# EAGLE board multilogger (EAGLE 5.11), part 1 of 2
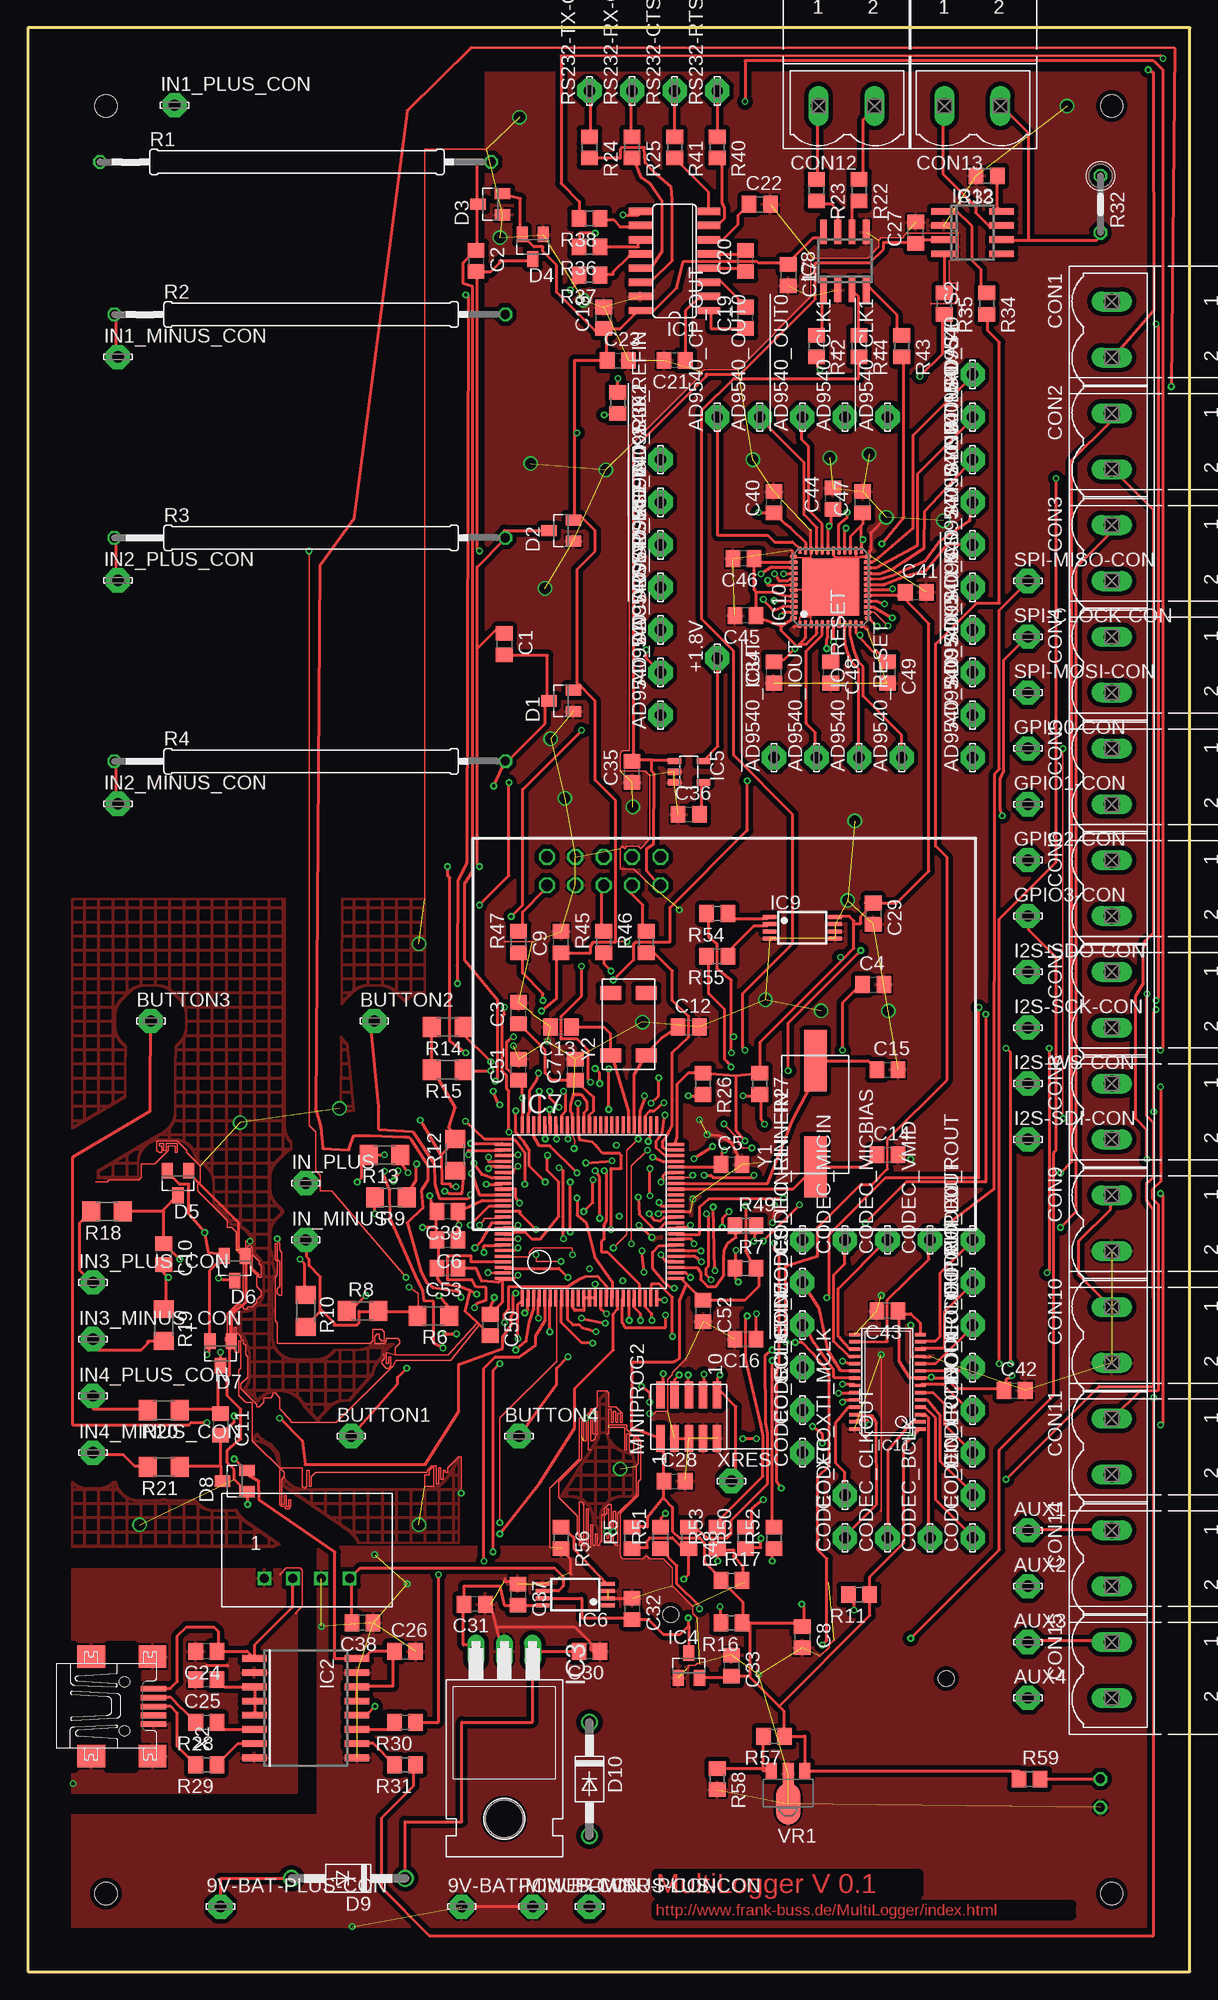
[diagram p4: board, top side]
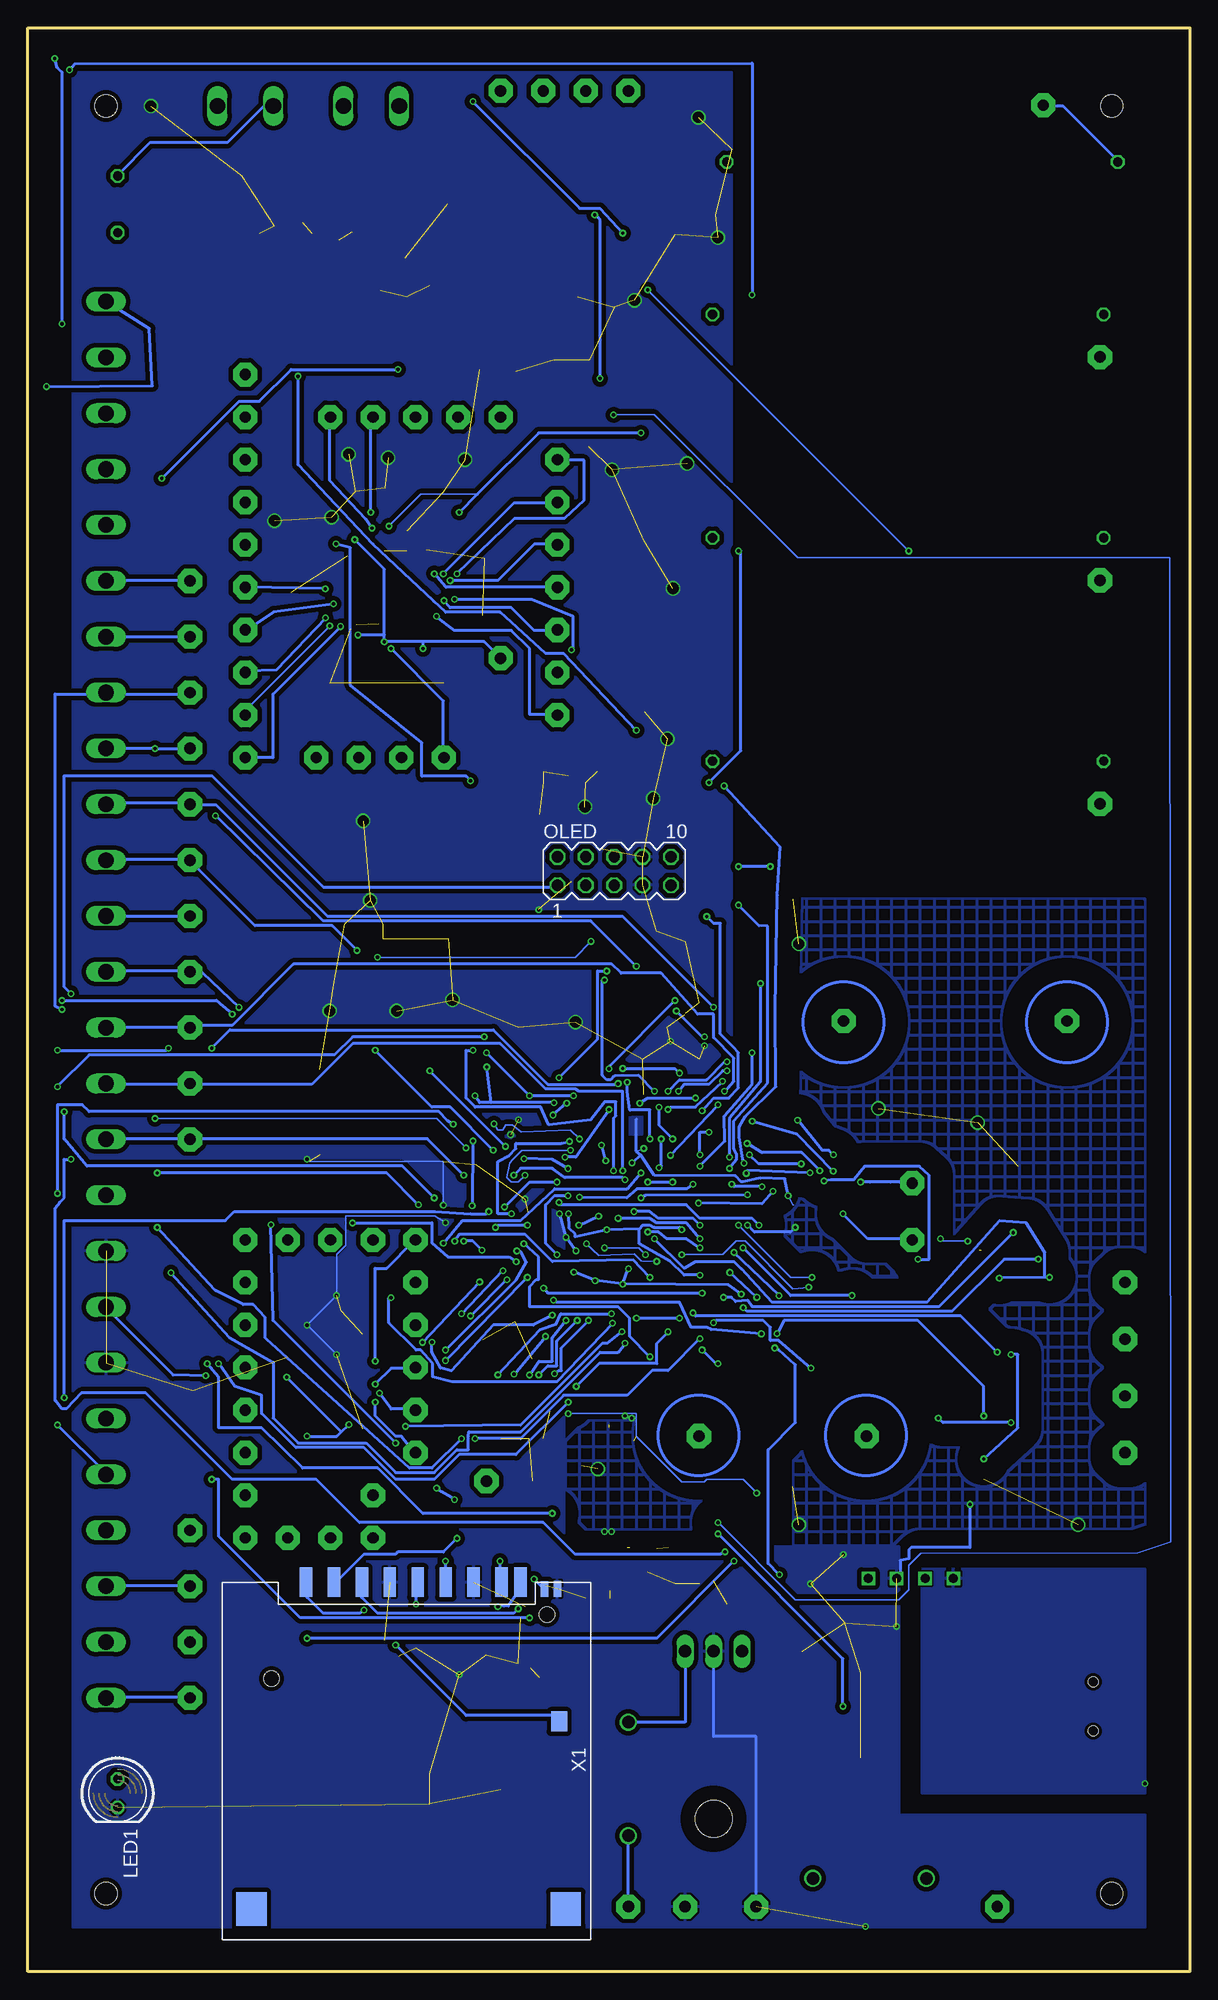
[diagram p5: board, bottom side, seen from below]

Size 104 x 174 mm. Coordinates in mm from the lower left corner, seen from the top.
Outline: 0,0 104,0 104,174 0,174 0,0
Copper layers (1*16): Top 0.035mm / dielectric 1.5mm / Bottom 0.035mm
Design rules "PCB-POOL Standard": minimum track width 0.15mm, minimum drill 0.3mm, track to track 0.15mm, track to pad 0.15mm, pad to pad 0.15mm, via to via 0.15mm, smd to smd 0.15mm, copper to edge 0.3mm, drill to drill 0.2mm, minimum pad ring 0.2mm, minimum via ring 0.15mm, stop-mask expansion 0.075mm, vias tented up to drill 0mil, thermal gap 0.2mm
Holes 2 mm at 7,167 97,167 7,7 97,7

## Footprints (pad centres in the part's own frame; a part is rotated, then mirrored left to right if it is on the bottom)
LSP10 = drill 1.016 pad 2.159 octagon: MP 0,0
C0805 = smd 1.3 x 1.5: 1 -0.95,0; 2 0.95,0
MSTBV2 = drill 1.397 long: 1 -2.5,0; 2 2.5,0
SOT23 = smd 1 x 1.4: 1 -0.95,-1.1; 2 0.95,-1.1; 3 0,1.1
DO41-10 = drill 1.118 round: A 5.08,0; C -5.08,0
SO16 = smd 0.66 x 2.032: 1 -4.445,-3.073; 2 -3.175,-3.073; 3 -1.905,-3.073; 4 -0.635,-3.073; 5 0.635,-3.073; 6 1.905,-3.073; 7 3.175,-3.073; 8 4.445,-3.073; 9 4.445,3.073; 10 3.175,3.073; 11 1.905,3.073; 12 0.635,3.073; 13 -0.635,3.073; 14 -1.905,3.073; 15 -3.175,3.073; 16 -4.445,3.073
SO-16W = smd 0.6 x 2.2: 1 -4.445,-4.6; 2 -3.175,-4.6; 3 -1.905,-4.6; 4 -0.635,-4.6; 5 0.635,-4.6; 6 1.905,-4.6; 7 3.175,-4.6; 8 4.445,-4.6; 9 4.445,4.6; 10 3.175,4.6; 11 1.905,4.6; 12 0.635,4.6; 13 -0.635,4.6; 14 -1.905,4.6; 15 -3.175,4.6; 16 -4.445,4.6
TO220H = drill 1.118 long: 1 -2.54,-10.16; 2 0,-10.16; 3 2.54,-10.16 | hole 3.302: 0,4.826
SOT23-DBV = smd 0.55 x 1.2: 1 -0.95,-1.3; 2 0,-1.3; 3 0.95,-1.3; 4 0.95,1.3; 5 -0.95,1.3
TSSOP8 = smd 1.2 x 0.35: 1 -2.925,0.975; 2 -2.925,0.325; 3 -2.925,-0.325; 4 -2.925,-0.975; 5 2.925,-0.975; 6 2.925,-0.325; 7 2.925,0.325; 8 2.925,0.975
TQFP100 = smd 0.27 x 1.5: 1 -6,-7.75; 2 -5.5,-7.75; 3 -5,-7.75; 4 -4.5,-7.75; 5 -4,-7.75; 6 -3.5,-7.75; 7 -3,-7.75; 8 -2.5,-7.75; 9 -2,-7.75; 10 -1.5,-7.75; 11 -1,-7.75; 12 -0.5,-7.75; 13 0,-7.75; 14 0.5,-7.75; 15 1,-7.75; 16 1.5,-7.75; 17 2,-7.75; 18 2.5,-7.75; 19 3,-7.75; 20 3.5,-7.75; 21 4,-7.75; 22 4.5,-7.75; 23 5,-7.75; 24 5.5,-7.75; 25 6,-7.75; 51 6,7.75; 52 5.5,7.75; 53 5,7.75; 54 4.5,7.75; 55 4,7.75; 56 3.5,7.75; 57 3,7.75; 58 2.5,7.75; 59 2,7.75; 60 1.5,7.75; 61 1,7.75; 62 0.5,7.75; 63 0,7.75; 64 -0.5,7.75; 65 -1,7.75; 66 -1.5,7.75; 67 -2,7.75; 68 -2.5,7.75; 69 -3,7.75; 70 -3.5,7.75; 71 -4,7.75; 72 -4.5,7.75; 73 -5,7.75; 74 -5.5,7.75; 75 -6,7.75 | smd 1.5 x 0.27: 26 7.75,-6; 27 7.75,-5.5; 28 7.75,-5; 29 7.75,-4.5; 30 7.75,-4; 31 7.75,-3.5; 32 7.75,-3; 33 7.75,-2.5; 34 7.75,-2; 35 7.75,-1.5; 36 7.75,-1; 37 7.75,-0.5; 38 7.75,0; 39 7.75,0.5; 40 7.75,1; 41 7.75,1.5; 42 7.75,2; 43 7.75,2.5; 44 7.75,3; 45 7.75,3.5; 46 7.75,4; 47 7.75,4.5; 48 7.75,5; 49 7.75,5.5; 50 7.75,6; 76 -7.75,6; 77 -7.75,5.5; 78 -7.75,5; 79 -7.75,4.5; 80 -7.75,4; 81 -7.75,3.5; 82 -7.75,3; 83 -7.75,2.5; 84 -7.75,2; 85 -7.75,1.5; 86 -7.75,1; 87 -7.75,0.5; 88 -7.75,0; 89 -7.75,-0.5; 90 -7.75,-1; 91 -7.75,-1.5; 92 -7.75,-2; 93 -7.75,-2.5; 94 -7.75,-3; 95 -7.75,-3.5; 96 -7.75,-4; 97 -7.75,-4.5; 98 -7.75,-5; 99 -7.75,-5.5; 100 -7.75,-6
SO08 = smd 0.6 x 2.2: 1 -1.905,-2.6; 2 -0.635,-2.6; 3 0.635,-2.6; 4 1.905,-2.6; 5 1.905,2.6; 6 0.635,2.6; 7 -0.635,2.6; 8 -1.905,2.6
LFCSP48 = smd 0.6 x 0.32: 1 -3.325,2.75; 12 -3.325,-2.75; 25 3.325,-2.75; 36 3.325,2.75 | smd 0.7 x 0.32: 2 -3.3,2.25; 3 -3.3,1.75; 4 -3.3,1.25; 5 -3.3,0.75; 6 -3.3,0.25; 7 -3.3,-0.25; 8 -3.3,-0.75; 9 -3.3,-1.25; 10 -3.3,-1.75; 11 -3.3,-2.25; 26 3.3,-2.25; 27 3.3,-1.75; 28 3.3,-1.25; 29 3.3,-0.75; 30 3.3,-0.25; 31 3.3,0.25; 32 3.3,0.75; 33 3.3,1.25; 34 3.3,1.75; 35 3.3,2.25 | smd 0.32 x 0.6: 13 -2.75,-3.325; 24 2.75,-3.325; 37 2.75,3.325; 48 -2.75,3.325 | smd 0.32 x 0.7: 14 -2.25,-3.3; 15 -1.75,-3.3; 16 -1.25,-3.3; 17 -0.75,-3.3; 18 -0.25,-3.3; 19 0.25,-3.3; 20 0.75,-3.3; 21 1.25,-3.3; 22 1.75,-3.3; 23 2.25,-3.3; 38 2.25,3.3; 39 1.75,3.3; 40 1.25,3.3; 41 0.75,3.3; 42 0.25,3.3; 43 -0.25,3.3; 44 -0.75,3.3; 45 -1.25,3.3; 46 -1.75,3.3; 47 -2.25,3.3 | smd 5.1 x 5.1: EXP 0,0
TSSOP28 = smd 0.305 x 0.991: 1 -4.225,-2.918; 2 -3.575,-2.918; 3 -2.925,-2.918; 4 -2.275,-2.918; 5 -1.625,-2.918; 6 -0.975,-2.918; 7 -0.325,-2.918; 8 0.325,-2.918; 9 0.975,-2.918; 10 1.625,-2.918; 11 2.275,-2.918; 12 2.925,-2.918; 13 3.575,-2.918; 14 4.225,-2.918; 15 4.225,2.918; 16 3.575,2.918; 17 2.925,2.918; 18 2.275,2.918; 19 1.625,2.918; 20 0.975,2.918; 21 0.325,2.918; 22 -0.325,2.918; 23 -0.975,2.918; 24 -1.625,2.918; 25 -2.275,2.918; 26 -2.925,2.918; 27 -3.575,2.918; 28 -4.225,2.918
SOIC8 = smd 0.6 x 2.2: 1 -1.905,-2.6; 2 -0.635,-2.6; 3 0.635,-2.6; 4 1.905,-2.6; 5 1.905,2.6; 6 0.635,2.6; 7 -0.635,2.6; 8 -1.905,2.6
DC-DC-CONVERTER = drill 0.8 square: 1 -3.81,0; 2 -1.27,0; 3 1.27,0; 4 3.81,0
LED5MM = drill 0.813 octagon: A -1.27,0; K 1.27,0
PIN-HEADER-50-MIL-2X5 = smd 2.4 x 0.76: 1 -2.54,2.54; 2 1.36,2.54; 3 -2.54,1.27; 4 1.36,1.27; 5 -2.54,0; 6 1.36,0; 7 -2.54,-1.27; 8 1.36,-1.27; 9 -2.54,-2.54; 10 1.36,-2.54
MA05-2 = drill 1.016 octagon: 1 -5.08,-1.27; 2 -5.08,1.27; 3 -2.54,-1.27; 4 -2.54,1.27; 5 0,-1.27; 6 0,1.27; 7 2.54,-1.27; 8 2.54,1.27; 9 5.08,-1.27; 10 5.08,1.27
0207/35 = drill 0.813 octagon: 1 -7.62,0; 2 27.38,0
R0805 = smd 1.3 x 1.5: 1 -0.95,0; 2 0.95,0
R1206 = smd 1.6 x 1.803: 1 -1.422,0; 2 1.422,0
0207/5V = drill 0.813 octagon: 1 -2.54,0; 2 2.54,0
SOT89 = smd 1 x 1.5: 1 -1.499,-1.981; 3 1.499,-1.981 | smd 1 x 2: 2 0,-1.727 | smd 2.2 x 3.7: 2@1 0,0.94
FPS009-3000 = smd 2.65 x 1.1: 1 -10,-20; 2 -10,-17.5; 3 -10,-15; 4 -10,-12.5; 5 -10,-10; 6 -10,-7.5; 7 -10,-5; 8 -10,-3.3; 9 -10,-22.5 | smd 1.4 x 0.7: COM_TERM -9.396,0; DETECT -9.385,-1.159 | smd 3 x 2.7: M1 19.249,-27.387; M2 19.251,0.741 | smd 1.8 x 1.45: WRITE_PROT 2.464,0.152 | hole 1.4: -7.098,-0.925; -1.38,-25.585
TYCO = smd 2.3 x 0.5: 1 2.9,1.75; 2 2.9,0.95; 3 2.9,0.15; 4 2.9,-0.65; 5 2.9,-1.45 | smd 2.5 x 2: M1 -2.7,-4.3; M2 -2.7,4.6; M3 2.8,4.6; M4 2.8,-4.3 | hole 0.9: 0.3,2.35; 0.3,-2.05
ECS-CRYSTAL = smd 5.5 x 2: 1 -4.9,0.1; 2 4.6,0.1
ABS25-CRYSTAL = smd 1.27 x 1.905: 1 -2.54,0; 2 3.048,0; 3 3.048,3.175; 4 -2.54,3.175

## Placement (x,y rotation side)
9V-BAT-MINUS-CON  LSP10  [LSP10]  38.83,5.81 0 top
9V-BAT-PLUS-CON  LSP10  [LSP10]  17.24,5.81 0 top
!AD9540_CLK1  LSP10  [LSP10]  76.93,139.16 90 top
!AD9540_CLK2  LSP10  [LSP10]  56.61,131.54 90 top
!AD9540_CS  LSP10  [LSP10]  84.55,120.11 90 top
!AD9540_IOUT  LSP10  [LSP10]  66.77,108.68 90 top
!AD9540_OUT0  LSP10  [LSP10]  69.31,139.16 90 top
!AD9540_REFIN  LSP10  [LSP10]  56.61,123.92 90 top
!CODEC_CS  LSP10  [LSP10]  69.31,57.88 90 top
!XRES  LSP10  [LSP10]  62.96,43.91 0 top
+1.8V  LSP10  [LSP10]  61.69,117.57 90 top
AD9540_CLK1  LSP10  [LSP10]  73.12,139.16 90 top
AD9540_CLK2  LSP10  [LSP10]  56.61,127.73 90 top
AD9540_CP_OUT  LSP10  [LSP10]  61.69,139.16 90 top
AD9540_CP_RSET  LSP10  [LSP10]  56.61,120.11 90 top
AD9540_DAC_RSET  LSP10  [LSP10]  56.61,112.49 90 top
AD9540_DRV_RSET  LSP10  [LSP10]  56.61,116.3 90 top
AD9540_IO_RESET  LSP10  [LSP10]  74.39,108.68 90 top
AD9540_IO_UPDATE  LSP10  [LSP10]  84.55,131.54 90 top
AD9540_IOUT  LSP10  [LSP10]  70.58,108.68 90 top
AD9540_OUT0  LSP10  [LSP10]  65.5,139.16 90 top
AD9540_REFIN  LSP10  [LSP10]  56.61,135.35 90 top
AD9540_RESET  LSP10  [LSP10]  78.2,108.68 90 top
AD9540_S0  LSP10  [LSP10]  84.55,135.35 90 top
AD9540_S1  LSP10  [LSP10]  84.55,139.16 90 top
AD9540_S2  LSP10  [LSP10]  84.55,142.97 90 top
AD9540_SCLK  LSP10  [LSP10]  84.55,116.3 90 top
AD9540_SD0  LSP10  [LSP10]  84.55,108.68 90 top
AD9540_SDIO  LSP10  [LSP10]  84.55,112.49 90 top
AD9540_SYNC_IN  LSP10  [LSP10]  84.55,127.73 90 top
AD9540_SYNC_OUT  LSP10  [LSP10]  84.55,123.92 90 top
AUX1  LSP10  [LSP10]  89.5,39.5 0 top
AUX2  LSP10  [LSP10]  89.5,34.5 0 top
AUX3  LSP10  [LSP10]  89.5,29.5 0 top
AUX4  LSP10  [LSP10]  89.5,24.5 0 top
BUTTON1  LSP10  [LSP10]  28.94,47.93 0 top
BUTTON2  LSP10  [LSP10]  31,85.1 0 top
BUTTON3  LSP10  [LSP10]  11,85.1 0 top
BUTTON4  LSP10  [LSP10]  43.94,47.93 0 top
C1  2n2  [C0805]  42.64,118.84 270 top
C2  2n2  [C0805]  40.1,153.13 270 top
C3  1 µ  [C0805]  43.91,85.82 90 top
C4  10 µ  [C0805]  75.66,88.36 0 top
C5  100 n  [C0805]  62.96,72.26 0 top
C6  1 µ  [C0805]  37.56,65.5 180 top
C7  100 n  [C0805]  48.99,80.74 90 top
C8  100n  [C0805]  69.31,29.94 270 top
C9  100n  [C0805]  47.72,92.17 90 top
C10  100 p  [C0805]  12.16,64.23 270 top
C11  100 p  [C0805]  17.24,48.99 270 top
C12  5 p  [C0805]  59.15,84.55 0 top
C13  5 p  [C0805]  47.72,84.55 180 top
C14  22 p  [C0805]  76.93,73.12 0 top
C15  22 p  [C0805]  76.93,80.74 0 top
C16  2n2  [C0805]  64.23,56.61 180 top
C17  100 n  [C0805]  68.04,151.86 270 top
C18  100 n  [C0805]  51.53,148.05 90 top
C19  100 n  [C0805]  64.23,148.05 90 top
C20  100 n  [C0805]  64.23,153.13 90 top
C21  100 n  [C0805]  57.88,144.24 180 top
C22  100 n  [C0805]  65.5,158.21 0 top
C23  10 µ  [C0805]  52.8,144.24 0 top
C24  100n  [C0805]  15.97,28.67 180 top
C25  100n  [C0805]  15.97,26.13 180 top
C26  100n  [C0805]  33.75,28.67 0 top
C27  100 n  [C0805]  79.47,155.67 90 top
C28  100n  [C0805]  57.88,43.91 0 top
C29  100 n  [C0805]  75.66,94.71 270 top
C30  1 µ  [C0805]  50.26,28.67 180 top
C31  100n  [C0805]  40,32.89 180 top
C32  1 µ  [C0805]  54.07,32.48 270 top
C33  1 µ  [C0805]  62.96,27.4 270 top
C34  1 µ  [C0805]  66.77,116.3 90 top
C35  100n  [C0805]  54.07,107.41 90 top
C36  10 n  [C0805]  59.15,103.6 0 top
C37  100n  [C0805]  43.86,33.75 270 top
C38  100n  [C0805]  29.94,31.21 180 top
C39  100 n  [C0805]  37.56,68.04 180 top
C40  100 n  [C0805]  66.77,131.54 90 top
C41  100 n  [C0805]  79.47,123.48 0 top
C42  100 n  [C0805]  88.31,52.04 0 top
C43  100 n  [C0805]  76.93,59.15 180 top
C44  1 µ  [C0805]  72.05,131.86 90 top
C45  100 n  [C0805]  64.23,121.38 180 top
C46  100 n  [C0805]  64.05,126.49 180 top
C47  100 n  [C0805]  74.69,131.54 90 top
C48  100 n  [C0805]  71.85,116.3 270 top
C49  1 µ  [C0805]  76.93,116.3 270 top
C50  1 µ  [C0805]  41.37,57.88 270 top
C51  100 n  [C0805]  43.91,80.74 90 top
C52  100 n  [C0805]  60.42,59.15 270 top
C53  100 n  [C0805]  37.56,62.96 180 top
CODEC_BCLK  LSP10  [LSP10]  80.74,38.83 90 top
CODEC_CLKOUT  LSP10  [LSP10]  76.93,38.83 90 top
CODEC_DIN  LSP10  [LSP10]  84.55,38.83 90 top
CODEC_DOUT  LSP10  [LSP10]  84.55,46.45 90 top
CODEC_LHPOUT  LSP10  [LSP10]  84.55,54.07 90 top
CODEC_LLINEIN  LSP10  [LSP10]  69.31,61.69 90 top
CODEC_LOUT  LSP10  [LSP10]  84.55,61.69 90 top
CODEC_LRCIN  LSP10  [LSP10]  84.55,42.64 90 top
CODEC_LRCOUT  LSP10  [LSP10]  84.55,50.26 90 top
CODEC_MICBIAS  LSP10  [LSP10]  76.93,65.5 90 top
CODEC_MICIN  LSP10  [LSP10]  73.12,65.5 90 top
CODEC_MODE  LSP10  [LSP10]  69.31,54.07 90 top
CODEC_RHPOUT  LSP10  [LSP10]  84.55,57.88 90 top
CODEC_RLINEIN  LSP10  [LSP10]  69.31,65.5 90 top
CODEC_ROUT  LSP10  [LSP10]  84.55,65.5 90 top
CODEC_SCLK  LSP10  [LSP10]  69.31,46.45 90 top
CODEC_SDIN  LSP10  [LSP10]  69.31,50.26 90 top
CODEC_VMID  LSP10  [LSP10]  80.74,65.5 90 top
CODEC_XTI_MCLK  LSP10  [LSP10]  73.12,42.64 90 top
CODEC_XTO  LSP10  [LSP10]  73.12,38.83 90 top
CON1  [MSTBV2]  97,147 270 top
CON2  [MSTBV2]  97,137 270 top
CON3  [MSTBV2]  97,127 270 top
CON4  [MSTBV2]  97,117 270 top
CON5  [MSTBV2]  97,107 270 top
CON6  [MSTBV2]  97,97 270 top
CON7  [MSTBV2]  97,87 270 top
CON8  [MSTBV2]  97,77 270 top
CON9  [MSTBV2]  97,67 270 top
CON10  [MSTBV2]  97,57 270 top
CON11  [MSTBV2]  97,47 270 top
CON12  [MSTBV2]  73.27,167 0 top
CON13  [MSTBV2]  84.54,167 0 top
CON14  [MSTBV2]  97,37 270 top
CON15  [MSTBV2]  97,27 270 top
D1  BAV199  [SOT23]  47.72,113.76 90 top
D2  BAV199  [SOT23]  47.72,129 90 top
D3  BAV199  [SOT23]  41.37,158.21 90 top
D4  BAV199  [SOT23]  45.18,154.4 180 top
D5  BAV199  [SOT23]  13.43,70.58 180 top
D6  BAV199  [SOT23]  18.51,62.96 180 top
D7  BAV199  [SOT23]  17.24,55.34 180 top
D8  BAV199  [SOT23]  18.51,43.91 90 top
D9  1N4004  [DO41-10]  28.67,8.35 180 top
D10  1N4004  [DO41-10]  50.26,17.24 270 top
GPIO0-CON  LSP10  [LSP10]  89.5,109.5 0 top
GPIO1-CON  LSP10  [LSP10]  89.5,104.5 0 top
GPIO2-CON  LSP10  [LSP10]  89.5,99.5 0 top
GPIO3-CON  LSP10  [LSP10]  89.5,94.5 0 top
I2S-SCK-CON  LSP10  [LSP10]  89.5,84.5 0 top
I2S-SDI-CON  LSP10  [LSP10]  89.5,74.5 0 top
I2S-SDO-CON  LSP10  [LSP10]  89.5,89.5 0 top
I2S-WS-CON  LSP10  [LSP10]  89.5,79.5 0 top
IC1  MAX3232CSE  [SO16]  57.88,153.13 90 top
IC2  ADUM4160  [SO-16W]  24.86,23.59 270 top
IC3  7805T  [TO220H]  42.64,18.51 180 top
IC4  MCP1703CB  [SOT23]  59.15,27.4 0 top
IC5  TPS79118  [SOT23-DBV]  59.15,107.41 270 top
IC6  TPS2112  [TSSOP8]  48.99,33.75 180 top
IC7  PSOC5  [TQFP100]  50.26,68.04 0 top
IC8  ST3485E  [SO08]  73.12,153.13 0 top
IC9  SE95  [TSSOP8]  69.31,93.44 0 top
IC10  AD9540  [LFCSP48]  71.85,123.92 90 top
IC11  TLV320AIC23  [TSSOP28]  76.93,52.8 90 top
IC12  SN65HVD232D  [SOIC8]  84.55,155.67 270 top
IC13  DC-DC-CONVERTER  [DC-DC-CONVERTER]  24.98,35.19 0 top
IN1_MINUS_CON  LSP10  [LSP10]  8.05,144.54 0 top
IN1_PLUS_CON  LSP10  [LSP10]  13.13,167.08 0 top
IN2_MINUS_CON  LSP10  [LSP10]  8.05,104.54 0 top
IN2_PLUS_CON  LSP10  [LSP10]  8.05,124.54 0 top
IN3_MINUS_CON  LSP10  [LSP10]  5.81,56.61 0 top
IN3_PLUS_CON  LSP10  [LSP10]  5.81,61.69 0 top
IN4_MINUS_CON  LSP10  [LSP10]  5.81,46.45 0 top
IN4_PLUS_CON  LSP10  [LSP10]  5.81,51.53 0 top
IN_MINUS  LSP10  [LSP10]  24.86,65.5 0 top
IN_PLUS  LSP10  [LSP10]  24.86,70.58 0 top
LED1  [LED5MM]  95.98,15.97 270 bottom
MINIPROG2  PIN-HEADER  [PIN-HEADER-50-MIL-2X5]  59.15,50.26 90 top
OLED  OLED  [MA05-2]  51.53,98.52 0 bottom
POWER-MINUS-CON  LSP10  [LSP10]  45.18,5.81 0 top
POWER-PLUS-CON  LSP10  [LSP10]  50.26,5.81 0 top
R1  10 Meg  [0207/35]  14.08,162 0 top
R2  10 Meg  [0207/35]  15.35,148.35 0 top
R3  10 Meg  [0207/35]  15.35,128.35 0 top
R4  10 Meg  [0207/35]  15.35,108.35 0 top
R5  10 k  [R0805]  54.07,38.83 90 top
R6  10 Meg  [R1206]  36.29,58.71 180 top
R7  10 k  [R0805]  64.23,62.96 0 top
R8  1 Meg  [R1206]  29.94,59.15 0 top
R9  100 k  [R1206]  32.48,69.31 180 top
R10  10 k  [R1206]  24.86,59.15 270 top
R11  50 k  [R0805]  74.39,33.75 180 top
R12  10 Meg  [R1206]  38.26,73.12 90 top
R13  1 Meg  [R1206]  31.91,73.12 180 top
R14  100 k  [R1206]  37.56,84.55 180 top
R15  10 k  [R1206]  37.56,80.74 180 top
R16  50 k  [R0805]  62.96,31.21 180 top
R17  50 k  [R0805]  62.96,35.02 0 top
R18  100 k  [R1206]  7.08,68.04 180 top
R19  100 k  [R1206]  12.16,57.88 270 top
R20  100 k  [R1206]  12.16,50.26 180 top
R21  100 k  [R1206]  12.16,45.18 180 top
R22  100  [R0805]  74.39,159.48 270 top
R23  100  [R0805]  70.58,159.48 270 top
R24  100  [R0805]  50.26,163.29 270 top
R25  100  [R0805]  54.07,163.29 270 top
R26  2k2  [R0805]  60.42,79.47 270 top
R27  2k2  [R0805]  65.5,79.47 270 top
R28  24  [R0805]  15.97,22.32 180 top
R29  24  [R0805]  15.97,18.51 180 top
R30  24  [R0805]  33.75,22.32 180 top
R31  24  [R0805]  33.75,18.51 180 top
R32  60  [0207/5V]  95.98,158.21 270 top
R33  10k  [R0805]  85.82,160.75 180 top
R34  33  [R0805]  85.82,149.32 270 top
R35  33  [R0805]  82.01,149.32 270 top
R36  24  [R0805]  50.26,154.4 180 top
R37  24  [R0805]  50.26,151.86 180 top
R38  24  [R0805]  50.26,156.94 180 top
R39  24  [R0805]  52.8,140.43 270 top
R40  100  [R0805]  61.69,163.29 270 top
R41  100  [R0805]  57.88,163.29 270 top
R42  24  [R0805]  70.58,145.51 270 top
R43  24  [R0805]  78.2,145.51 270 top
R44  24  [R0805]  74.39,145.51 270 top
R45  24  [R0805]  51.53,92.17 90 top
R46  24  [R0805]  55.34,92.17 90 top
R47  24  [R0805]  43.91,92.17 90 top
R48  24  [R0805]  59.15,38.83 270 top
R49  24  [R0805]  64.23,66.77 0 top
R50  24  [R0805]  64.23,38.83 90 top
R51  24  [R0805]  56.61,38.83 90 top
R52  24  [R0805]  66.77,38.83 90 top
R53  24  [R0805]  61.69,38.83 90 top
R54  24  [R0805]  61.69,94.71 180 top
R55  24  [R0805]  61.69,90.9 180 top
R56  825  [R0805]  47.72,38.83 270 top
R57  2700  [R0805]  66.77,21.05 180 top
R58  6800  [R0805]  61.69,17.24 270 top
R59  330  [R0805]  89.63,17.24 0 top
RS232-CTS-CON  LSP10  [LSP10]  57.88,168.37 90 top
RS232-RTS-CON  LSP10  [LSP10]  61.69,168.37 90 top
RS232-RX-CON  LSP10  [LSP10]  54.07,168.37 90 top
RS232-TX-CON  LSP10  [LSP10]  50.26,168.37 90 top
SPI-CLOCK-CON  LSP10  [LSP10]  89.5,119.5 0 top
SPI-MISO-CON  LSP10  [LSP10]  89.5,124.5 0 top
SPI-MOSI-CON  LSP10  [LSP10]  89.5,114.5 0 top
VR1  [SOT89]  68.04,15.97 180 top
X1  SD-CARD  [FPS009-3000]  56.61,24.86 270 bottom
X2  MINI-USB-SHIELD-UX60-MB-5ST  [TYCO]  8.35,23.59 0 top
Y1  24 MHz  [ECS-CRYSTAL]  70.58,76.93 90 top
Y2  32.768 kHz  [ABS25-CRYSTAL]  55.34,84.55 90 top

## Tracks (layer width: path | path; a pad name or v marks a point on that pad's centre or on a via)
!XRES  (via drill 0.3)
  Top 0.254: v51.78,58.9 51.25,59.3 51.25,60.12 IC7.15 | v61.94,53.41 61.74,53.21 61.74,52.19 | 61.74,52.19 61.74,51.78 MINIPROG2.10 61.74,52.19 | 61.74,52.19 63.37,50.56 63.37,44.47 62.96,44.06 !XRES.MP
  Bottom 0.254: v51.78,58.9 56.3,58.9 56.71,57.98 58.13,57.47 v61.94,53.41
+1.8V  (via drill 0.3)
  Top 0.254: v72.1,119.04 72.1,117.5 C48.1 | v72.1,119.04 IC10.7 | IC10.11 74.12,119.84 74.29,119.63 | 74.29,119.63 75.56,118.23 75.95,118.23 C49.1 | IC10.27 73.6,128.46 74.6,129.46 | C47.1 74.75,130.54 74.75,129.61 74.6,129.46 | 74.6,128.19 IC10.25 | 74.6,128.19 74.6,129.46 | IC10.38 65.47,126.17 C46.1 64.99,126.36 64.99,123.72 65.19,123.51 | 67.43,120.47 65.39,121.17 C45.1 65.19,121.48 65.19,123.51 | 67.43,120.47 IC10.48 | 65.19,123.51 66.82,123.51 67.55,123.23 68.45,123.11 IC10.44 | 68.85,118.64 v68.65,118.43 67.63,117.42 66.82,117.42 C34.2 | 68.85,118.64 69.06,118.84 | 69.06,118.84 69.6,119.45 69.6,120.47 IC10.2 | 69.06,118.84 69.67,118.84 70.48,119.65 70.61,119.83 70.61,120.47 IC10.4 | 68.85,118.64 67.43,120.06 67.43,120.47 | IC5.5 60.52,108.48 61.74,109.7 61.74,117.42 +1.8V.MP | v72.1,119.04 | v74.75,128.19 74.6,128.19 | v74.47,119.65 74.29,119.63
  Bottom 0.254: 68.65,119.04 63.16,119.04 +1.8V.MP | 68.65,119.04 v72.1,119.04 72.1,119.65 | v74.75,128.19 72.1,125.55 72.1,119.65 | 72.1,119.65 v74.47,119.65 | 68.65,119.04 v68.65,118.43
+3V3  (via drill 0.3)
  Top 0.15: 52.6,92.22 v53.61,92.22 | v72.71,90.8 72.92,90.59
  Top 0.254: IC4.2 62.96,26.3 C33.2 64.59,26.45 | 64.59,26.45 64.59,31.26 63.98,31.26 | 63.98,31.26 63.91,31.26 R16.1 | R16.1 69.31,31.21 C8.1 69.46,31.06 69.46,32.68 v69.26,32.89 | R59.1 88.68,17.95 VR1.1 69.54,21.1 69.46,21.1 69.46,21.05 R57.1 67.63,21.1 67.63,23.34 67.23,23.74 | IC7.26 58.48,62.04 58.94,61.58 | 58.94,61.58 C52.1 64.16,60.1 65.4,61.33 65.4,62.74 R7.2 64.99,62.96 64.24,64.47 64.23,67.41 64.23,68.45 v64.24,68.57 | IC7.100 42.51,59.97 C50.1 41.22,58.9 41.22,59.1 v41.74,60.36 | IC7.100 42.45,62.01 42.13,61.69 40.61,61.82 40.13,62.93 39.75,62.93 C53.1 | v44.26,78.2 IC7.75 | v44.26,78.2 44.26,79.44 C51.1 43.86,79.83 42.84,80.84 42.84,83.2 v43.45,83.69 | IC10.17 77.77,123.17 78.14,123.23 | 78.14,123.23 C41.1 | IC10.31 71.6,129.31 v71.7,129.41 71.9,129.61 71.9,130.44 C44.1 | 80.84,53.12 IC11.8 79.7,53.14 78.91,53.14 78,54.63 78,58.9 C43.1 78.13,58.9 79.01,58.9 79.85,58.06 IC11.14 | 80.84,53.12 82.14,53.12 83.08,52.19 87.21,52.19 C42.1 87.55,52.19 87.55,53 v88.08,53.35 | 51.78,147.09 51.55,147.09 C18.1 | 51.78,147.09 53,147.09 54.6,148.69 IC1.16 54.83,148.51 55.85,148.51 58.08,150.74 58.66,153.12 65.25,153.12 65.39,152.98 68.04,152.98 | 63.37,80.17 R26.1 60.32,80.44 59.1,80.44 58.08,79.42 58.08,74.69 57.88,74.14 IC7.50 | 63.37,80.17 R27.1 65.5,83.18 72.92,90.59 73.93,91.61 73.93,93.85 | 73.93,93.85 73.93,94.05 73.53,94.46 72.28,94.46 IC9.8 | C29.1 74.93,95.66 | C29.1 77.78,95.66 80.64,98.52 80.64,120.67 78.14,123.23 | IC10.35 69.6,127.92 68.24,129.25 67.75,129.61 C40.1 66.62,130.63 v65.4,130.63 | 56.86,42.39 55.44,40.61 55.44,39.8 54.22,39.8 R5.2 | 56.86,42.39 56.86,43.86 C28.1 56.86,44.06 56.86,47.52 56.66,47.72
  Top 0.254: 56.66,47.72 54.02,48.74 54.05,54.55 57.7,54.55 57.91,54.6 58.29,54.88 58.29,60.1 58.94,61.58 | 56.66,47.72 MINIPROG2.1 | 63.98,31.26 63.98,33.09 62.15,34.92 R17.1 61.94,35.12 61.94,35.25 60.52,36.67 60.52,38.37 60.14,38.83 58.31,38.83 57.68,39.39 57.68,41.57 56.86,42.39 | 63.98,31.26 R16.1 | 67.23,23.74 64.59,26.38 64.59,26.45 | CON10.1 96.89,59.51 94.05,62.35 94.05,65.4 96.89,68.24 96.89,69.46 CON9.1 | 79.22,47.92 78.4,47.11 78.4,38.37 75.36,35.33 75.36,33.9 R11.1 75.36,33.7 75.36,31.87 67.23,23.74 | 79.22,47.92 79.83,48.53 IC11.1 | v75.28,48.95 75.15,49.35 74.14,49.35 IC11.27 | 79.22,47.92 v79.01,47.92 | v80.84,53.21 80.84,53.12 | IC2.13 29.43,24.35 29.43,25.37 IC2.14 29.64,25.57 32.68,25.57 32.68,28.62 C26.1 30.7,28.67 30.04,28.01 29.48,28.01 IC2.16 29.43,28.01 27.46,28.01 27.46,37.56 20.69,42.23 20.67,43.88 19.68,44.47 19.68,44.67 D8.2 19.48,44.88 v18.46,45.89 | v16.02,55.24 16.22,55.44 16.22,56.25 D7.2 16.29,62.79 D6.2 17.44,64.18 16.17,64.34 v15.82,66.16 14.39,67.84 14.39,70.48 13.58,70.48 12.57,71.49 D5.2 | v45.48,66.41 44.06,67.84 44.06,68.04 IC7.88 | v43.86,62.35 43.45,61.94 42.64,61.94 IC7.100 | v55.61,67.84 56.04,67.27 56.61,67.22 56.93,67.53 57.88,67.53 IC7.37 | 47.72,91.2 47.31,90.8 47.31,87.09 v45.97,86 | v49.24,77.74 49.27,77.59 49.27,75.97 IC7.65 49.27,75.76 49.4,74.44 50.15,74.31 50.53,74.25 50.77,74.01 51.02,73.69 51.47,73.25 52.93,73.25 53.12,73.06 53.12,71.91 52.19,71.9 v52.19,66.41 | v44.27,78.2 v44.26,78.2 | 73.93,93.85 74.54,93.85 74.54,94.46 75.56,95.47 C29.1 | 68.04,152.98 70.28,155.21 71.09,155.21 71.09,155.62 IC8.8
  Top 0.254: D3.2 42.64,159.07 44.06,158.72 44.06,155.62 D4.2 44.27,155.42 45.28,154.4 46.09,154.4 46.09,153.99 47.31,152.77 47.31,150.34 50.77,146.88 51.38,146.88 51.38,147.09 C18.1 | 51.78,144.24 51.78,147.09 | 51.78,147.09 C18.1 | 49.14,115.39 49.14,125.55 50.77,127.17 50.77,129 49.55,130.22 48.94,130.22 | 49.14,115.39 49.14,114.98 48.94,114.78 D1.2 | 48.94,130.22 48.94,130.02 D2.2 48.94,130.22 | 51.78,144.24 48.94,144.24 48.94,137.74 | 48.94,130.22 48.94,137.74 | 51.78,144.24 C23.1 | 68.04,152.98 C17.1 | 48.94,137.74 v49.14,137.74 | 47.72,91.2 50.36,91.2 50.36,91.81 50.58,92.16 52.6,92.16 52.6,92.22 52.6,104.82 50.77,106.65 50.77,113.76 49.14,115.39 | 47.72,91.2 C9.1 | v64.18,74.35 63.37,75.36 63.37,80.17 | 63.37,80.17 63.37,80.18
  Bottom 0.15: v71.7,129.41 68.85,132.25 63.77,132.25 | v53.61,92.22 55.03,90.8 v72.71,90.8
  Bottom 0.254: v69.26,32.89 69.26,34.72 X1.4 | 75.97,48.33 76.37,47.92 v79.01,47.92 | 75.97,48.33 v75.28,48.95 | 75.97,48.33 v80.84,53.21 | v88.08,53.35 91,53.41 96.89,59.3 CON10.1 | v18.46,45.89 15.41,48.69 15.41,55.24 v16.02,55.24 | v45.48,66.41 45.69,66.62 47.94,66.62 48.33,66.82 48.99,66.82 49.27,66.48 | 49.27,66.48 49.27,65.16 46.5,63.57 45.28,62.35 v43.86,62.35 | v55.61,67.84 55.53,66.52 55.03,66.02 55.03,65.78 v52.19,66.41 49.27,66.48 | v45.97,86 43.66,83.69 v43.45,83.69 | v49.24,77.74 48.53,78.2 v44.27,78.2 | v65.4,130.63 63.77,132.25 58.29,137.74 v49.14,137.74 | v41.74,60.36 41.05,60.36 40.67,59.98 39.59,60.1 39.19,59.51 22.47,59.51 v15.82,66.16 | v64.18,74.35 v64.24,68.57
+5V  (via drill 0.3)
  Top 0.254: IC6.7 49.55,33.42 49.55,31.67 54.07,31.67 C32.2 55.53,31.53 56.86,30.19 58.39,30.19 59.15,30.96 | 59.15,30.96 IC4.3 | 59.15,30.96 59.15,31.53 59.1,31.53 v59.1,31.67 | IC12.3 79.78,155.03 C27.1 79.42,154.81 76.57,154.81 76.57,154.2 75.36,152.98 70.48,152.98 70.48,149.73 63.77,143.02 60.73,143.02 60.73,142.82 54.22,136.31 54.22,108.48 | 55.85,108.48 54.22,108.48 | 55.85,108.48 57.68,108.48 IC5.1 | 55.85,108.48 55.85,107.46 56.05,107.26 56,100.93 55.37,100.53 55.39,98.52 56.46,97.3 OLED.1 | 54.22,108.48 C35.2 | v87.55,44.06 95.88,52.39 100.75,52.39 100.73,68.19 100.12,68.98 100.12,70.56 100.78,71.09 100.75,75.97 100.15,76.57 v100.15,87.55
  Bottom 0.254: v59.1,31.67 79.62,31.67 86.94,38.98 86.94,44.06 v87.55,44.06 | v100.15,87.55 100.75,88.16 100.75,107.05 87.55,107.05 77.59,97.1 56.66,97.1 OLED.1
+5V/2
  Top 0.254: IC13.2 23.71,32.65 20.29,29.23 20.29,28.06 IC2.1 19.62,28.67 C24.1 17.04,28.79 17.04,30.45 16.63,30.85 14.19,30.85 13.38,30.04 13.38,25.98 12.74,25.34 X2.1
CAN_RX  (via drill 0.3)
  Top 0.254: v43.86,64.79 43.66,64.59 42.64,64.59 IC7.95 | v48.53,66.21 v48.53,70.68 | v46.3,70.68 44.88,72.1 44.88,73.53 44.32,74.34 44.06,74.62 43.66,75.15 v43.66,77.06 | v43.25,94.46 44.27,95.47 44.27,105.83 v49.55,111.12 | v79.83,142.82 81.86,144.85 81.86,148.3 R35.2
  Bottom 0.254: v43.86,64.79 45.05,65.6 46.79,65.6 47.53,66.21 v48.53,66.21 | v48.53,70.68 v46.3,70.68 | v43.66,77.06 42.64,78.2 41.26,78.2 40.41,79.11 40.41,82.26 40.81,82.71 42.03,83.93 42.03,93.85 42.64,93.85 v43.25,94.46 | v49.55,111.12 56.05,118 57.68,118 61.74,121.69 66.62,121.69 67.7,122.69 73.12,127.79 79.83,134.89 v79.83,142.82
CAN_TX  (via drill 0.3)
  Top 0.203: 76.92,71.84 76.92,74.48
  Top 0.254: v57.07,58.76 57.07,57.68 53.42,57.68 53.21,58.08 53.21,60.12 IC7.19 | v67.84,56.34 67.84,63.19 70.68,64.05 70.68,66.62 74.54,70.48 75.56,70.48 76.92,71.84 | 76.92,74.48 82.26,79.83 82.26,99.74 81.25,100.75 81.25,118.84 84.91,122.5 86.94,122.5 86.94,145.87 85.92,146.88 85.92,148.3 R34.2
  Bottom 0.254: v57.07,58.76 58.77,57.88 62.38,57.88 66.1,53.78 67.08,54.03 67.84,55.49 v67.84,56.34
CANH
  Top 0.254: IC12.7 86,156.31 84.83,157.47 84.83,157.98 81.88,160.93 81.88,166.84 CON13.1
  Bottom 0.254: R32.1 95.88,160.9 93.03,163.75 86.12,163.75 82.87,167 82.06,167 CON13.1
CANL
  Top 0.254: 89.58,155.01 95.67,155.01 95.88,155.21 95.88,155.62 R32.2 | 89.58,155.01 87.34,155.01 IC12.6 | 89.58,155.01 89.58,164.56 87.14,167 CON13.2
CMOD  (via drill 0.3)
  Top 0.254: v65.19,58.9 65.19,56.66 C16.1 | v61.49,62.76 v61.33,68.45 | v56.66,70.68 56.86,70.89 56.86,71.29 57.07,71.49 57.88,71.49 IC7.45
  Bottom 0.254: v65.19,58.9 v61.49,62.76 | v61.33,68.45 59.1,70.68 v56.66,70.68
D1KM  (via drill 0.3)
  Top 0.254: v39.63,74.14 42.44,74.14 IC7.76 | v33.13,71.7 33.13,71.44 v32.75,70.78 | v24.35,63.77 24.76,63.37 24.76,60.73 R10.1
  Bottom 0.254: v39.63,74.14 38.31,73.32 34.75,73.32 v33.13,71.7 | v32.75,70.78 32.11,70.89 30.08,70.89 29.13,72.09 24.21,72.09 23.35,71.29 23.35,63.77 v24.35,63.77
D1KP  (via drill 0.3)
  Top 0.254: v45.76,78.81 45.76,75.77 IC7.72 | v41.42,80.64 38.98,80.64 R15.1
  Bottom 0.254: v45.76,78.81 45.28,79.42 43.05,79.42 41.83,80.64 v41.42,80.64
D1M  (via drill 0.3)
  Top 0.254: v40.81,64.38 40.81,64.99 42.44,64.99 IC7.94 | v36.77,60.51 37.56,59.53 37.56,59.3 R6.1
  Bottom 0.254: v36.77,60.51 v40.81,64.38
D1P  (via drill 0.3)
  Top 0.254: v43.99,68.8 43.66,69.26 43.66,70.07 42.64,70.07 IC7.84 | v37.31,69.87 37.7,69.67 38.85,69.67 39.05,71.7 R12.1
  Bottom 0.254: v43.99,68.8 38.31,68.74 v37.31,69.87
D10M  (via drill 0.3)
  Top 0.254: v40,64.79 40.61,65.4 41.55,67.05 42.44,67.02 IC7.90 | v30.25,60.52 29.03,59.3 28.62,59.3 R8.1
  Bottom 0.254: v40,64.79 35.73,60.52 v30.25,60.52
D10P  (via drill 0.3)
  Top 0.254: v39.71,71.46 40.41,69.54 42.44,69.54 IC7.85 | v34.02,71.51 33.33,72.51 R13.1 | R13.1
  Bottom 0.254: v39.71,71.46 39.63,71.7 v34.02,71.51
D100M  (via drill 0.3)
  Top 0.254: v39.43,73.12 39.43,73.53 42.44,73.53 IC7.77 | v34.79,72.31 34.75,71.7 34.75,70.89 33.9,69.46 R9.1
  Bottom 0.254: v39.43,73.12 38.61,72.31 v34.79,72.31
D100P  (via drill 0.3)
  Top 0.254: v46.3,74.54 46.3,75.76 IC7.71 | v47.52,77.39 46.7,78.2 v46.7,78.81 | v41.42,81.45 38.98,83.89 38.98,84.5 R14.1
  Bottom 0.254: v46.3,74.54 47.52,75.76 v47.52,77.39 | v46.7,78.81 45.69,79.83 43.25,79.83 41.62,81.45 v41.42,81.45
DM  (via drill 0.3)
  Top 0.254: v36.75,35.53 36.75,22.32 R30.1 | v37.15,55.82 36.34,56.25 36.31,59.98 35.47,60.04 35.35,61 34.91,61.88 32.43,67.43 32.4,69.93 31.83,71.34 v31.92,71.65 | v39.17,76.12 40.86,74.54 43.4,74.54 43.66,74.39 44.47,73.32 v44.47,70.49 | v54.63,69.32 54.7,67.79 56.04,66.45 56.48,66.45 57.05,67.02 57.88,67.02 IC7.36
  Bottom 0.254: v36.75,35.53 37.76,36.54 37.76,46.7 35.33,49.14 35.33,54.32 36.82,55.63 v37.15,55.82 | v31.92,71.65 35.16,74.95 v39.17,76.12 | v44.47,70.49 45.08,70.07 49.51,70.07 50.45,69.26 v54.63,69.32
DP  (via drill 0.3)
  Top 0.254: v100.75,51.38 100.75,3.22 35.93,3.22 31.67,7.49 31.67,13.79 34.51,16.63 34.51,18.46 R31.1 | v62.76,68.04 62.15,67.43 v62.15,66.62 | v59.3,66.82 59.1,66.62 58.08,66.62 IC7.35
  Bottom 0.254: v100.75,51.38 100.75,67.23 86.33,67.23 85.52,68.04 67.57,68.04 64.38,67.84 62.96,67.84 v62.76,68.04 | v62.15,66.62 61.94,66.82 v59.3,66.82
GND  (via drill 0.3, 0.3 pad 0.25, 1)  (127 unrouted)
  Top 0.15: 45.19,85.69 45.08,85.72 45.13,85.83 | 50.36,46.7 50.16,46.7 50.16,49.75 50.56,50.16 50.97,50.16 50.97,48.13 50.77,47.92 50.77,47.72 50.56,47.52 50.36,47.52 50.36,49.75 50.56,49.95 50.77,49.95 50.77,48.13 50.56,48.13 v50.56,49.75 | v49.95,49.55 49.95,47.52 49.75,47.52 49.75,49.35 49.55,49.35 49.55,45.89 47.52,43.86 47.52,42.44 49.14,40.81 49.14,39.19 49.35,38.98 49.35,38.58 49.55,38.37 49.75,38.37 49.75,41.83 49.55,42.03 49.35,42.03 49.35,39.19 49.55,38.98 49.55,38.58 49.35,38.37 49.35,38.17 49.95,38.17 49.95,41.42 50.16,41.42 50.16,37.97 | 50.36,37.97 50.36,40 50.56,40 50.56,38.17 50.77,38.17 50.77,39.19 50.97,39.19 50.97,38.17 51.17,38.17 51.17,38.37 51.38,38.58 51.38,40.81 51.58,41.01 51.58,41.42 51.99,41.83 52.19,41.83 52.19,38.58 51.58,38.58 51.58,40.81 51.78,41.01 51.78,41.42 51.99,41.42 51.99,38.78 51.78,38.78 v51.78,39.39 | v52.39,39.39 52.39,41.22 52.6,41.22 52.6,39.19 52.39,38.98 52.39,38.37 52.6,38.17 52.8,38.17 52.8,41.01 54.43,42.64 54.43,45.28 54.63,45.48 54.63,47.52 53.61,48.53 53.61,48.94 51.99,48.94 51.99,50.36 52.19,50.36 52.19,49.14 52.39,49.14 52.39,50.16 52.6,50.16 52.6,49.14 52.8,49.14 52.8,49.95 53,49.95 53,49.14 53.21,49.14 53.21,49.95 52.6,50.56 51.99,50.56 51.99,51.78 51.78,51.99 50.97,51.99 50.97,50.56 50.77,50.36 50.36,50.36 50.36,50.16 49.75,49.55 49.35,49.55 49.35,45.89 46.7,43.25 46.7,37.97 | 51.78,48.13 51.99,48.13 51.99,48.74 53.41,48.74 53.41,46.7 53.61,46.7 53.61,48.13 53.82,48.13 53.82,46.7 54.02,46.5 54.22,46.5 54.22,47.72 54.43,47.92 54.63,47.92 54.63,47.72 54.83,47.52 54.83,44.06 54.63,43.86 54.63,42.64 53,41.01 53,37.15 53.21,36.95 55.03,36.95 55.24,37.15 55.44,37.15 55.65,36.95 56.86,36.95 57.68,36.14 57.68,34.51 59.51,32.68 59.51,32.07 59.91,31.67 59.93,31.65
  Top 0.15: v79.01,57.88 79.01,55.03 79.83,55.03 IC11.11 | v76.37,55.24 76.37,41.22 76.32,41.25 | 72.16,29.6 72.1,29.64 71.7,29.23 71.7,29.03 70.89,28.21 70.82,28.27 | v48.89,73.69 48.95,74.42 48.74,74.95 48.74,75.76 IC7.66 | 68.45,127.17 68.34,127.16 | 70.07,126.56 68.65,126.56 IC10.37 | 70.07,126.56 70.07,127.17 IC10.34 | 70.07,123.92 70.07,126.56 | 70.07,123.72 70.07,123.92 | 70.07,121.28 70.07,123.72 | 70.07,121.28 70.07,120.67 IC10.3 | 74.95,120.26 75.06,120.23 | 70.07,123.72 68.65,123.72 IC10.43 | 70.07,123.92 IC10.EXP | 70.07,121.28 69.06,121.28 69.06,120.67 IC10.1 | 41.01,163.14 35.53,163.14 35.53,96.08 35.51,96 | 32.89,55.19 32.07,55.44 32.07,54.43 32.28,54.43 32.28,55.03 32.48,55.03 32.48,54.22 32.28,54.02 32.07,54.02 31.67,54.43 31.67,54.63 31.87,54.83 31.87,55.24 31.79,55.27 | 32.89,55.19 37.62,55.19 40.2,58.08 40.23,58.11 | 60.14,27.53 60.12,27.6 59.91,27.6 59.71,27.4 59.1,27.4 59.1,27.2 59.01,27.13 | 42.64,92.22 45.08,92.22 45.11,92.17 | 32.89,55.19 32.89,55.85 33.29,56.25 33.29,56.46 33.09,56.66 32.07,56.66 32.07,56.46 31.87,56.25 31.06,56.25 31.06,56.86 31.26,57.07 31.46,57.07 31.46,56.66 31.67,56.46 31.87,56.46 31.87,57.27 31.67,57.47 30.85,57.47 30.85,56.46 30.65,56.25 22.32,56.25 22.32,58.08 22.12,58.29 22.12,62.15 22.32,62.35 22.32,63.57 22.12,63.77 22.12,65.19 22.32,65.19 22.32,63.77 22.52,63.57 22.52,61.33 22.32,61.13 22.32,60.73 22.52,60.52 22.73,60.52 22.73,64.38 22.52,64.59 22.52,65.19 22.32,65.4 v22.32,65.6 | v19.88,65.4 19.48,65.4 19.48,64.38 19.88,63.98 19.88,62.96 20.69,62.15 20.9,62.15 20.9,63.16 20.69,63.37 20.69,63.57 20.09,64.18 20.09,64.79 19.88,64.99 19.68,64.99 19.68,64.38 20.09,63.98 20.09,62.96 20.69,62.35 20.49,62.15 20.49,61.33 20.9,60.93 20.9,60.52 20.49,60.12 20.49,59.91 20.09,59.51 19.68,59.51 19.68,59.3 19.27,59.3 19.27,59.51 19.07,59.71 18.87,59.71 18.05,58.9 18.05,56.66 17.85,56.46 17.65,56.46 17.65,56.66 17.85,56.86 17.85,58.9 19.27,60.32 19.27,63.77 19.07,63.98 19.07,64.18 18.66,64.59 18.66,66.21 18.26,66.62 17.85,66.62 17.85,67.23 15.21,69.87 15.21,70.48 15.41,70.68 15.41,72.1 14.19,73.32 14.19,73.53 13.38,74.34 11.55,74.34 11.55,73.53 11.75,73.32 11.96,73.32 11.96,73.53 12.16,73.73 12.16,74.14 11.75,74.14 11.75,73.93 11.96,73.93 11.96,73.73 12.16,73.53 12.36,73.53 12.36,74.14 13.38,74.14 13.38,73.32 13.18,73.32 13.18,73.93 12.57,73.93 12.57,73.53 11.35,72.31 10.13,72.31 10.13,71.09 9.93,70.89 7.28,70.89 7.08,70.68 6.06,70.68
  Top 0.15: 53.21,100.75 53,100.55 53,98.72 54.22,98.72 55.24,97.71 55.31,97.61 | v38.78,42.84 38.78,46.09 38.58,46.09 37.56,45.08 37.56,44.67 37.36,44.67 37.36,44.88 37.15,44.88 37.15,44.06 36.95,44.06 36.95,45.08 36.75,45.08 36.75,43.66 36.54,43.66 36.54,45.28 36.34,45.28 35.93,44.88 35.93,44.47 35.53,44.47 35.53,43.45 36.34,43.45 36.34,45.08 36.14,45.28 35.73,44.88 35.73,44.67 25.77,44.67 25.37,44.27 25.37,43.45 25.16,43.45 25.16,44.88 24.96,44.88 24.96,43.45 24.76,43.25 24.55,43.45 24.55,45.08 22.73,45.08 22.52,44.88 22.52,41.83 22.73,41.62 22.93,41.62 23.13,41.42 23.34,41.42 23.54,41.62 23.54,42.23 23.34,42.23 23.34,41.62 23.13,41.62 23.13,42.64 22.93,42.64 22.93,41.83 22.73,41.83 22.73,44.06 22.93,44.27 22.93,44.67 20.09,47.52 20.09,50.97 19.48,50.97 18.87,51.58 18.87,53.82 19.07,54.02 19.07,56.46 18.87,56.46 18.87,55.44 18.66,55.44 18.46,55.65 18.46,57.68 18.66,57.68 18.66,57.27 19.07,56.86 19.07,56.66 19.27,56.46 19.27,56.25 19.48,56.05 19.48,55.24 19.68,55.03 19.68,53.21 19.07,52.6 19.07,52.19 20.49,50.77 20.49,50.56 20.69,50.56 21.1,50.97 21.1,51.38 21.71,51.38 21.91,51.58 21.91,51.78 22.12,51.78 22.52,51.38 22.52,50.36 23.54,49.35 23.54,49.14 27.6,49.14 32.68,54.22 32.94,54.73 37.83,54.73 40.41,57.88 40.43,57.9 | v55.65,49.95 56.05,49.95 | 56.05,49.95 56.25,50.16 57.27,50.16 57.27,53 57.68,53.41 57.68,53.61 58.9,54.83 58.93,54.7 | 56.05,49.95 56,49.9 | 53.21,100.75 53.41,100.55 53.61,100.75 54.63,100.75 54.83,100.55 55.65,101.36 55.65,107.05 55.24,107.46 53,107.46 53,109.09 53.21,109.29 53.82,109.29 53.82,136.52 60.32,143.02 60.32,143.22 60.52,143.43 63.57,143.43 70.07,149.93 70.07,153.18 70.28,153.38 75.15,153.38 76.17,154.4 76.17,155.01 76.37,155.21 78.4,155.21 78.4,155.42 78.61,155.62 83.28,155.62 83.28,153.18 82.47,153.18 82.47,151.35 82.67,151.15 83.08,151.15 83.08,149.52 82.87,149.32 80.81,149.32
  Top 0.15: 53.21,100.75 53.26,100.73 | v66.63,67.05 v66.82,68.6
  Top 0.254: IC6.2 C32.1 | D5.1 14.39,71.49 18.87,67.02 18.87,64.59 19.27,64.18 D6.1 19.53,63.98 19.53,59.91 18.26,58.9 18.26,56.46 D7.1 18.05,56.25 18.05,53.41 17.85,53.21 17.85,51.55 19.07,50.34 19.07,47.68 17.85,46.65 17.85,45.56 18.46,44.95 18.46,44.06 19.48,43.05 D8.1 19.68,42.84 v19.68,41.83 | 36.75,62.96 36.75,65.4 C6.2 36.54,65.6 36.54,66.62 | 39.57,60.98 39.12,59.1 40.23,58.11 40.43,57.9 41.22,57.07 C50.2 | 39.57,60.98 39.48,60.98 38.7,61.31 36.99,61.56 36.75,61.87 36.7,62.06 36.7,62.33 36.52,62.33 36.75,62.96 | 36.75,62.96 C53.2 | v39.59,66.82 41.27,68.52 42.46,68.52 IC7.87 | 36.54,66.62 v35.33,66.62 | 50.77,60.32 50.36,60.32 IC7.13 50.16,60.32 49.75,60.32 IC7.12 49.75,60.12 49.75,59.17 48.94,59.17 48.74,59.51 48.74,60.12 IC7.10 | 48.74,75.97 IC7.66 48.74,76.8 48.57,76.97 48.57,77.59 48.86,78.52 49.56,78.52 50.01,77.88 50.01,77.12 49.75,76.87 IC7.64 | 74.14,126.56 72.31,126.56 72.1,126.77 72.1,127.17 IC10.30 | 74.14,126.56 74.14,127.17 IC10.26 | IC10.1 69.06,120.47 68.65,120.47 68.54,120.4 | IC10.12 74.75,120.47 74.95,120.26 75.12,120.17 | IC10.37 68.45,126.77 68.45,127.17 68.33,127.23 | IC10.43 68.45,123.72 68.41,123.72 68.27,123.7 | IC10.3 70.07,120.47 | IC10.34 70.07,127.37 70.07,129 | IC11.11 80.03,55.03 80.64,55.03 80.75,55.04 | 74.14,126.56 74.64,126.66 IC10.24 75.36,126.77 75.36,127.17 75.46,127.23 75.46,128.83 v76.82,130.19 | R56.2 47.72,37.76 48.53,36.95 48.53,35.73 48.64,35.59 | v35.96,69.46 36.34,68.24 36.54,68.04 C39.2 36.54,66.62 | 59.28,68.02 59.1,68.04 IC7.38 56.8,68.04 56.61,67.85 v56.42,67.85 | v50.77,61.54 50.77,60.32 | 50.77,60.32 IC7.14
  Top 0.254: MINIPROG2.3 MINIPROG2.5 | IC10.EXP 71.9,123.92 72.51,123.31 72.61,120.69 IC10.8 | 39.57,60.98 v40.16,60.65 | C37.1 43.86,34.92 42.64,34.92 42.71,35.12 | C5.2 62.9,74.26 61.88,74.83 v60.79,74.94 | v55.84,65.73 v54.7,66.81 | v55.14,62.62 v54.95,64.52 | v49.93,72.39 v52.28,72.58 | C31.1 41.42,32.89 41.95,30.78 | 41.95,30.78 42.23,29.64 42.64,29.64 IC3.2 | C30.1 51.17,28.82 50.36,28.82 50.36,29.43 48.94,30.85 42.23,30.85 41.95,30.78 | POWER-MINUS-CON.MP 45.08,5.86 38.98,5.86 9V-BAT-MINUS-CON.MP
  Bottom 0.15: v50.56,49.75 50.36,49.55 v49.95,49.55 | v52.39,39.39 v51.78,39.39 | v76.37,55.24 v79.01,57.88 v76.37,60.52 76.37,64.18 75.56,64.99 75.56,67.63 67.6,67.63 v66.63,67.05 | 49.55,73.44 v48.89,73.69 | v35.96,69.46 35.53,68.65 35.45,68.62 | v58.29,95.07 58.29,95.12 | v22.32,65.6 22.12,65.4 v19.88,65.4 | v38.78,42.84 40,44.06 43.25,44.06 43.45,43.86 45.48,43.86 49.55,47.92 49.55,49.95 v55.65,49.95 | v66.82,68.6 66.82,72.51 78.81,72.51 v79.01,72.71
  Bottom 0.254: v39.59,66.82 38.98,66.21 35.73,66.21 v35.33,66.62 | v35.96,69.46 36.27,70.97 38.44,71.04 40.04,70.71 40.16,70.71 40.67,71.22 47.92,71.29 49.17,73.11 | 49.17,73.11 49.55,73.44 49.55,76.33 | v40.16,60.65 40.23,60.67 40.29,60.74 41.29,61.47 v50.77,61.54 | v19.68,41.83 19.68,37.97 24.96,37.97 25.16,37.76 25.16,36.95 25.94,36.81 25.94,35.39 26.18,35.33 IC13.3 | v50.77,61.54 v50.25,62.93 | v50.77,61.54 v53.24,61.85 v55.14,62.62 | v54.95,64.52 v55.84,65.73 v56.42,67.85 | 49.17,73.11 v49.93,72.39 | v52.28,72.58 v52.66,73.98 | v54.7,66.81 v52.92,67.63 | 9V-BAT-MINUS-CON.MP 38.83,21.05 42.64,21.05 IC3.2
  other vias: 43.45,82.87 66,87 71,86 77,86 74,103 55,85 45,135 44,166 93,167 19,76 10,40 35,40 53,45 35,92 46.27,123.82 54.14,104.27 48.05,105.03 46.78,110.36 73.37,95.89 64.88,135.35 71.77,135.53 75.3,135.83 42.25,155.23 81.93,129.89 51.73,134.44 65.4,26.59 46.5,83.28 49.72,149.62 29.03,4.03 59.52,69.16 60.09,76.27 26.27,30.91 33.95,34.72 31.03,37.32 27.89,77.27
  pour Top (isolate 0.406, rank 2): 41,170 100,170 100,4 4,4 4,14 26,14 26,38 56,38 56,75 41,75
  pour Bottom (isolate 0.406, rank 2): 41,170 100,170 100,4 4,4 4,14 26,14 26,38 56,38 56,75 41,75
  pour Top (isolate 2, hatched): 4,96 41,96 41,75 56,75 56,38 4,38
  pour Bottom (isolate 2, hatched): 4,96 41,96 41,75 56,75 56,38 4,38
GND2  (via drill 0.3)
  Top 0.15: 22.52,35.53 23.13,36.14 24.35,36.14 24.55,35.93 24.55,32.68 23.95,32.07 24,32.01
  Top 0.254: 15.93,27.4 16.02,27.4 17.85,27.4 17.91,27.4
  other vias: 4.03,16.83
  pour Bottom: 4,36 24,36 24,16 4,16
  pour Top (isolate 0.406): 4,36 24,36 24,16 4,16
GPIO0  (via drill 0.3)
  Top 0.15: v48.74,64.18 48.74,64.79 45.28,64.79 44.88,64.38 44.88,63.98 42.64,63.98 IC7.96 | v52.39,64.79 53.61,66.01 53.61,73.53 v54.63,74.54 | v62.29,75.89 63.57,74.54 63.57,74.14 63.98,73.73 v64.79,73.73 | v92.63,76.37 v92.63,109.49
  Bottom 0.15: v48.74,64.18 49.35,64.79 v52.39,64.79 | v54.63,74.54 55.44,75.36 59.85,75.15 60.67,75.79 61.24,75.79 61.49,75.36 61.94,75.36 v62.29,75.89 | v64.79,73.73 67.43,76.37 v92.63,76.37
  Bottom 0.254: CON5.1 96.89,109.49 v92.63,109.49 89.58,109.49 GPIO0-CON.MP
GPIO1  (via drill 0.3)
  Top 0.254: v43.86,73.12 42.64,73.12 IC7.78 | v43.05,75.15 43.05,78.81 42.84,79.01 42.84,80.23 42.44,80.64 42.44,85.52 42.64,85.72 v42.64,86.33
  Bottom 0.254: v43.86,73.12 43.86,75.15 v43.05,75.15 | v42.64,86.33 50.77,94.46 77.18,94.46 87.14,104.41 89.38,104.41 GPIO1-CON.MP 89.58,104.62 96.89,104.62 CON5.2
GPIO2  (via drill 0.3)
  Top 0.254: v56.66,64.18 56.79,63.95 57.07,63.57 57.88,63.57 IC7.29 | v55.67,69.46 v55.67,71.89 | v59.61,72.78 v61.27,73.87 | v68.04,80.64 68.04,84.91 v74.54,91.41
  Bottom 0.254: v56.66,64.18 57.68,65.19 57.68,68.65 56.86,69.46 v55.67,69.46 | v55.67,71.89 57.07,72.71 v59.61,72.78 | v61.27,73.87 v68.04,80.64 | v74.54,91.41 76.78,93.64 83.69,93.64 89.38,99.33 GPIO2-CON.MP 89.58,99.54 96.89,99.54 CON6.1
GPIO3  (via drill 0.3)
  Top 0.254: v40.81,36.75 40.81,54.02 41.83,55.03 44.04,55.03 45.43,56.08 45.43,56.89 46.3,58.29 46.3,60.12 IC7.5 | v79.01,29.84 86.94,37.76 86.94,46.7 91.81,51.58 91.81,73.32 92.02,73.53 92.02,90.8 89.58,93.24 89.58,94.46 GPIO3-CON.MP
  Bottom 0.254: v40.81,36.75 47.72,29.84 v79.01,29.84 | CON6.2 96.89,94.46 89.58,94.46 GPIO3-CON.MP
I2C_SCL  (via drill 0.3)
  Top 0.254: v56.91,77.79 56.05,77.06 55.66,77.06 55.24,76.57 55.24,75.97 IC7.53 | v63.99,78.4 65.4,78.4 R27.2 65.6,78.4 65.6,76.37 v65.93,75.85 | v62.94,80.98 62.55,81.45 62.35,81.65 62.35,86.12 60.93,87.55 60.93,90.8 R55.2 | v101.36,48.94 101.57,49.14 101.57,69.46 v101.36,69.67
  Bottom 0.254: 62.55,77.79 63.57,77.79 v63.99,78.4 | v56.91,77.79 62.55,77.79 | 62.55,77.79 v62.94,80.98 | v101.36,48.94 97.1,44.67 CON11.2 | v101.36,69.67 101.36,77.59 99.13,77.59 98.52,76.98 67.23,76.98 66.41,76.17 v65.93,75.85
I2C_SDA  (via drill 0.3)
  Top 0.254: v55.17,78.4 55.24,78.2 54.78,77.01 54.76,75.97 IC7.54 | v59.1,78.4 60.32,78.4 R26.2 | v62.96,82.26 62.96,83.69 | 62.96,83.69 62.96,88.77 61.68,89.8 61.68,92 60.93,92.63 60.93,94.66 R54.2 | v101.36,79.22 101.36,70.73 100.63,70 100.63,69.21 101.16,68.67 101.16,51.99 99.54,51.99 97.1,49.55 CON11.1 | 62.96,83.69 v63.16,83.69
  Bottom 0.254: v55.17,78.4 v59.1,78.4 v62.96,82.26 | v101.36,79.22 98.52,82.06 76.57,82.06 74.95,83.69 v63.16,83.69
I2S_SCK  (via drill 0.3)
  Top 0.254: v46.5,73.07 46.5,71.7 47.52,70.68 47.52,67.63 45.87,65.6 45.08,65.6 44.47,66.21 43.53,66.21 43.33,66.01 42.64,66.01 IC7.92 | v42.23,77.59 42.03,77.79 v41.65,78.81
  Bottom 0.254: v46.5,73.07 v42.23,77.59 | v41.65,78.81 40.81,79.71 40.81,81.78 42.64,83.61 42.64,85.72 44.06,85.72 47.34,89.38 50.92,89.38 51.73,90.19 80.23,90.19 85.72,84.7 89.38,84.7 I2S-SCK-CON.MP 89.58,84.5 96.89,84.5 CON7.2
I2S_SDI  (via drill 0.3)
  Top 0.254: v43.86,66.82 43.86,66.62 42.64,66.62 IC7.91 | v49.75,68.04 50.56,68.85 v50.56,70.89 | v60.52,71.29 61.13,71.29 61.33,71.09 64.99,71.09 v64.99,71.29
  Bottom 0.254: v43.86,66.82 44.47,67.43 47.53,67.43 48.33,68.04 v49.75,68.04 | v50.56,70.89 50.77,71.09 55.94,71.09 57.07,71.9 59.91,71.9 v60.52,71.29 | v64.99,71.29 68.24,74.54 89.38,74.54 I2S-SDI-CON.MP 89.58,74.54 96.89,74.54 CON8.2
I2S_SDO  (via drill 0.3)
  Top 0.254: v45.69,58.49 45.69,60.12 IC7.4 | v49.55,58.49 v51.67,58.05 | v71.49,60.32 71.7,60.52 71.7,66.01 76.78,71.09 85.11,71.09 v85.11,86.31
  Bottom 0.254: v45.69,58.49 v49.55,58.49 | v51.67,58.05 56.66,52.8 66.01,52.8 67.79,53.24 67.77,54.44 68.85,55.65 69.26,55.65 71.7,58.08 71.7,60.32 v71.49,60.32 | v85.11,86.31 88.36,89.38 89.38,89.38 I2S-SDO-CON.MP 89.58,89.58 96.89,89.58 CON7.1
I2S_WS  (via drill 0.3)
  Top 0.254: v43.86,65.6 42.64,65.6 IC7.93 | v51.17,67.43 51.17,71.09 50.9,71.49 v50.77,71.7
  Bottom 0.254: v43.86,65.6 45.09,67.02 47.73,67.02 48.33,67.43 v51.17,67.43 | v50.77,71.7 50.77,78.81 54.64,78.81 55.03,79.01 57.68,79.01 61.74,83.08 74.95,83.08 78.61,79.42 89.38,79.42 I2S-WS-CON.MP 89.58,79.42 96.89,79.42 CON8.1
IDAC  (via drill 0.3)
  Top 0.254: v41.22,72.92 41.22,72.51 42.44,72.51 IC7.79 | v38.44,88.45 38.42,90.05 38.49,97.63 39.26,99.3 39.39,149.96 v39.19,150.09 | v100.27,170.25 100.73,170 100.75,148.67 97.1,144.44 CON1.2
  Bottom 0.254: v41.22,72.92 41.22,76.37 38.44,79.66 v38.44,88.45 | v39.19,150.09 39.19,170.86 99.81,170.78 v100.27,170.25
IN1_MINUS  (via drill 0.3)
  Top 0.254: 40.2,152.16 41.42,152.16 42.23,152.98 42.23,153.18 45.08,153.18 D4.3 | v41.22,71.9 41.22,72.1 42.44,72.1 IC7.80 | v40.41,95.47 43.05,98.11 v43.05,106.44 | v40.41,127.17 40.2,127.37 40.2,148.51 | 40.2,148.51 40.2,152.16 | 40.2,152.16 C2.2 | 40.2,148.51 42.64,148.51 R2.2
  Bottom 0.254: v41.22,71.9 40.61,72.64 40.61,73.22 40.81,73.68 40.81,76.17 37.8,79.56 37.8,93.58 38.58,93.64 v40.41,95.47 | v43.05,106.44 40.2,109.29 40.2,127.17 v40.41,127.17
IN1_PLUS  (via drill 0.3)
  Top 0.254: v46.7,77.18 46.7,75.97 IC7.70 | v41.83,79.7 42.03,80.03 42.03,86.94 39.11,90.49 39.11,97.4 39.8,98.52 39.8,150.82 38.98,151.12 38.98,152.98 40,153.99 C2.1 40.2,154.2 40.2,158.06 D3.3 40.2,158.26 40.2,161.92 41.42,161.92 R1.2
  Bottom 0.254: v46.7,77.18 46.5,77.39 44.27,77.39 v41.83,79.7
IN2_MINUS  (via drill 0.3 pad 0.25)
  Top 0.254: 46.5,113.76 46.3,113.56 46.3,111.73 42.84,108.27 R4.2 v41.69,106.14 | 46.5,113.76 46.5,117.82 42.64,117.82 C1.2 | 46.5,113.76 D1.3 | IC7.82 41.5,71.03 40.61,71.34 v39.91,72.36
  Bottom 0.254: v39.91,72.36 40.04,72.74 40.35,74.71 40.35,75.6 39.78,76.55 37.05,79.22 37.12,86.2 36.92,96.36 36.67,100.68 v41.69,106.14
IN2_PLUS  (via drill 0.3)
  Top 0.254: D2.3 42.64,129 42.64,128.39 R3.2 42.64,128.19 40.2,125.75 40.2,118.43 | v43.86,72.1 43.45,71.7 43.45,71.49 42.64,71.49 IC7.81 | v39.19,82.26 37.76,83.31 37.76,97.91 37.56,98.11 v37.56,98.93 | v40.41,98.93 40.2,99.13 40.2,118.43 | 40.2,118.43 41.83,120.06 42.64,120.06 C1.1
  Bottom 0.254: v43.86,72.1 41.62,74.34 41.69,76.59 39.19,79.47 v39.19,82.26 | v37.56,98.93 v40.41,98.93
IN3_MINUS  (via drill 0.3)
  Top 0.254: v17.06,62.08 17.44,61.94 18.46,61.94 D6.3 | 12.36,62.35 12.16,62.55 C10.2 | v47.31,74.54 47.31,75.76 IC7.69 | v47.53,71.96 47.92,71.7 v47.92,65.6 | R19.1 12.36,59.51 12.36,62.35 | R19.1 | 12.36,62.35 v12.57,62.15
  Bottom 0.254: v12.57,62.15 12.97,62.15 | 12.97,62.15 v17.06,62.08 | v47.31,74.54 47.31,72.16 v47.53,71.96 | v47.92,65.6 45.28,62.96 44.35,63.47 44.29,63.53 40.8,63.53 40.15,62.88 40.12,62.88 37.4,59.91 23.54,59.91 17.06,67.22 14.66,67.02 12.97,64.38 12.97,62.15
IN3_PLUS  (via drill 0.3)
  Top 0.254: 12.16,65.19 12.16,68.04 | 12.16,68.04 12.16,68.24 13.38,69.46 D5.3 | v39.97,59.43 40.23,59.85 41,60.12 41,61.24 40.1,61.31 39.76,61.92 39.49,61.92 37.56,61.93 37.56,64.1 39.64,64.1 39.64,63.57 42.44,63.57 IC7.97 | 12.16,65.19 v13.58,63.77 | C10.1 12.16,65.19 | 12.16,68.04 R18.1
  Bottom 0.254: v39.97,59.43 39.59,59.1 21.3,59.1 16.63,63.77 v13.58,63.77
IN4_MINUS  (via drill 0.3)
  Top 0.254: 17.24,45.28 17.24,44.06 D8.3 | 17.24,45.28 C11.2 17.24,48.13 18.45,49.14 18.45,49.55 v18.46,49.75 | v56.97,60.12 56.25,60.12 IC7.25 | v38.36,57.09 37.97,57.1 v36.95,57.1 | 17.24,45.28 13.58,45.28 R21.1
  Bottom 0.254: v56.97,60.12 56.66,59.91 45.66,59.91 44.63,57.68 43.24,57.68 42.84,57.47 v38.36,57.09 | v36.95,57.1 36.34,58.29 24.35,58.29 18.46,52.39 v18.46,49.75
IN4_PLUS  (via drill 0.3)
  Top 0.254: 17.04,50.36 17.04,50.16 17.24,49.95 C11.1 17.04,50.36 | 17.04,50.36 17.04,54.02 17.24,54.22 D7.3 v17.24,55.44 | v44.47,58.96 44.74,59.23 44.74,60.24 IC7.2 | 17.04,50.36 13.58,50.36 R20.1
  Bottom 0.254: v44.47,58.96 44.27,58.69 20.49,58.69 v17.24,55.44
IN_MINUS  (via drill 0.3)
  Top 0.15: v59.51,71.29 59.51,71.09 58.08,71.09 IC7.44 | v55.44,73.53 54.02,72.1 v54.02,65.16 | v47.72,63.57 45.48,63.57 v45.48,64.18 | v34.12,61.26 34.92,60.73 34.92,59.3 R6.2
  Top 0.254: R6.2 34.72,59.1 31.46,59.1 R8.2 31.26,59.1 29.64,59.1 29.64,58.08 29.43,57.88 27.4,57.88 27.4,58.08 26.18,59.3 | 26.18,59.3 26.18,62.2 25.16,63.21 25.16,63.77 24.96,63.98 24.96,65.4 IN_MINUS.MP | 26.18,59.3 26.18,59.1 24.96,57.88 R10.2 | v31.06,67.84 31.06,69.26 R9.2
  Bottom 0.15: v59.51,71.29 60.12,70.68 60.73,70.68 61.13,71.09 60.88,72.4 60.61,72.71 59.8,73.53 v55.44,73.53 | v54.02,65.16 52.9,64.1 49.73,64.23 49.13,63.63 v47.72,63.57 | v45.48,64.18 41.83,64.18 40.61,65.4 39.8,65.4 35.53,61.13 v34.12,61.26
  Bottom 0.254: v31.06,67.84 28.82,65.6 24.96,65.6 IN_MINUS.MP
IN_PLUS  (via drill 0.3)
  Top 0.254: R13.2 29.88,72.51 29.88,71.09 v29.47,70.68 | R13.2 | R14.2 36.14,84.5 36.14,80.84 R15.2 36.34,80.64 38.25,77.34 37.67,75.51 38.41,74.54 R12.2 38.21,74.34 36.99,73.12 36.99,73.01 | v41.01,70.48 42.44,70.48 IC7.83 | v38.31,70.28 37.8,70.3 37.78,70.52 37.05,70.54 36.99,73.01 | v35.11,76.22 36.99,73.01 | R13.2 v31.91,73.12
  Bottom 0.254: v29.47,70.68 28.66,70.67 26.79,70.67 25.98,70.68 24.96,70.68 IN_PLUS.MP | v41.01,70.48 40.81,70.28 v38.31,70.28 | v31.91,73.12 32.31,73.53 32.92,73.53 v35.11,76.22
JTAG_TDI  (via drill 0.3)
  Top 0.254: v57.68,56.86 57.68,60.37 56.51,61.54 55.8,61.54 55.75,61.13 55.75,60.32 IC7.24 | v60.5,53.47 60.52,52.8 60.52,51.78 MINIPROG2.8
  Bottom 0.254: v60.5,53.47 v57.68,56.86
N$1
  Top 0.15: 7.89,128.19 R3.1 | IN2_PLUS_CON.MP 7.89,124.73
  Top 0.254: 7.89,124.73 7.89,128.19
N$2
  Top 0.15: 7.89,108.27 R4.1 | IN2_MINUS_CON.MP 7.89,104.62
  Top 0.254: 7.89,104.62 7.89,108.27
N$3
  Top 0.254: R33.1 86.77,157.96 IC12.8
N$4
  Top 0.254: CON14.1 96.89,39.59 89.58,39.59 AUX1.MP
N$5
  Bottom 0.15: R1.1 6.47,162.12 | 12.97,167 IN1_PLUS_CON.MP
  Bottom 0.254: 6.47,162.12 11.35,167 12.97,167
N$6
  Top 0.15: 7.89,148.3 R2.1 | IN1_MINUS_CON.MP 7.89,144.65
  Top 0.254: 7.89,144.65 7.89,148.3
N$7
  Top 0.254: IC8.6 73.75,157.9 R22.2
N$8
  Top 0.254: IC8.7 72.48,157.68 71.9,158.26 70.85,158.26 R23.2
N$9  (via drill 0.3)
  Top 0.254: v73.93,32.35 73.93,33.29 73.53,33.7 R11.2
  Bottom 0.254: v73.93,32.35 74.34,32.07 77.59,32.07 79.01,33.5 79.01,34.72 X1.9
N$10
  Bottom 0.254: CON14.2 96.89,34.51 89.58,34.51 AUX2.MP
N$11
  Top 0.254: CON15.1 96.89,29.64 89.58,29.64 AUX3.MP
N$12
  Bottom 0.254: CON15.2 96.89,24.55 89.58,24.55 AUX4.MP
N$13
  Top 0.254: C19.1 64.18,147.09 61.13,147.09 61.13,148.51 IC1.1
N$14
  Top 0.254: R34.1 85.72,150.34 85.31,150.74 85.31,152.37 84.5,153.18 84.5,156.23 83.08,157.65 82.06,157.65 IC12.1
N$15
  Top 0.254: R35.1 82.06,150.34 82.06,153.59 IC12.4
N$16
  Top 0.254: IC7.63 50.26,76.68 50.64,77.06 50.64,78.27 C7.1 46.94,79.79 46.3,80.44 46.3,82.48 C3.1
N$18
  Top 0.254: C19.2 64.18,149.12 61.94,151.35 61.13,151.35 IC1.3
N$20
  Top 0.254: R59.2 LED1.A
N$21  (via drill 0.3)
  Top 0.254: IC7.46 61.79,72.04 C5.1 62.15,72.31 62.15,73.32 v62.35,73.53 | v72.92,82.47 72.92,86.73 74.54,88.36 C4.1
  Bottom 0.254: v72.92,82.47 67.84,77.39 66.21,77.39 v62.35,73.53
N$22  (via drill 0.3)
  Top 0.254: IC7.86 40.65,69.04 C39.1 38.51,66.82 | C6.1 38.51,66.82 | v56.47,68.85 56.66,68.52 57.88,68.52 IC7.39 | 38.51,66.82 v38.58,66.82
  Bottom 0.254: v56.47,68.85 56.46,68.65 45.08,68.65 43.86,67.43 39.19,67.43 v38.58,66.82
N$23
